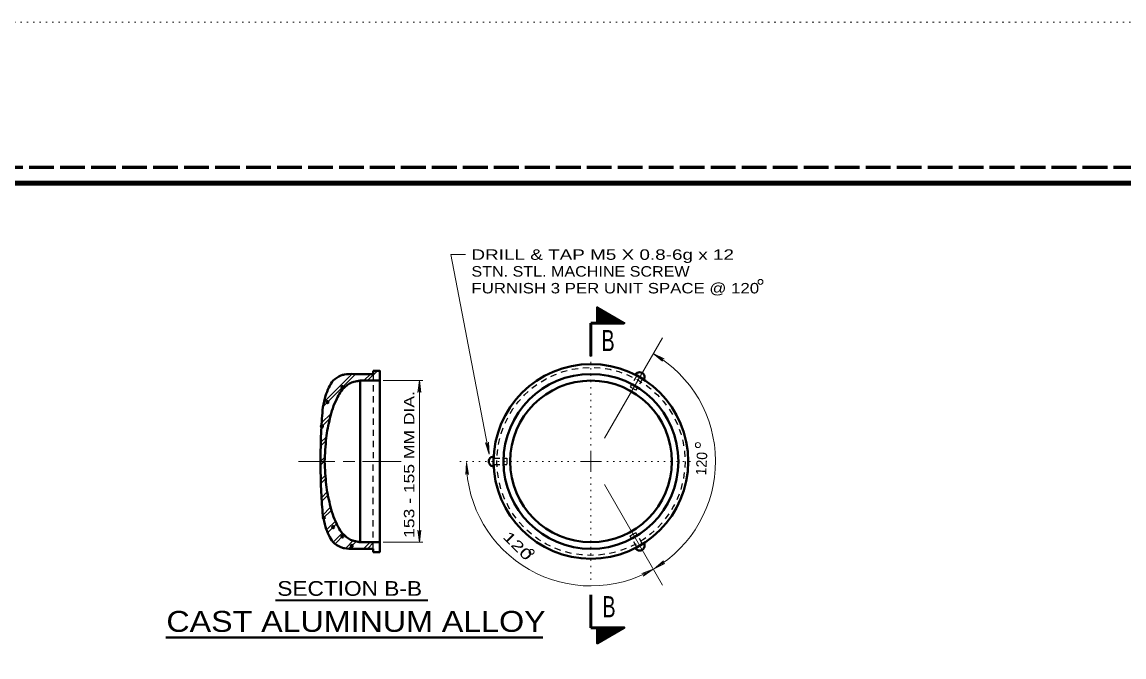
# Model space of a CAD drawing. Extents: x 312583 to 312854, y 144419 to 144597.
# Drawn here: x 312691.9 to 312772, y 144550.7 to 144596.8 of the extents above; entities that cross this region are included whole.
import ezdxf
from ezdxf.enums import TextEntityAlignment as Align

# ---------------------------------------------------------------- set-up
doc = ezdxf.new("R2010")
doc.units = 0
doc.header["$LTSCALE"] = 0.3
doc.header["$PDMODE"] = 32
doc.header["$PDSIZE"] = 0.15
for name, pattern in [('DOTTED', [1.5, 0.3, -1.2]), ('LONG_DASHED', [7.5, 6, -1.5]), ('SHORT_DASHED', [2.7, 1.5, -1.2])]:
    doc.linetypes.add(name, pattern=pattern)
for name, color, linetype, lineweight in [('1', 7, 'Continuous', 40), ('2', 7, 'Continuous', 13), ('62', 7, 'DOTTED', 13), ('63', 7, 'LONG_DASHED', 60)]:
    doc.layers.add(name, color=color, linetype=linetype, lineweight=lineweight)

msp = doc.modelspace()

# ---------------------------------------------------------------- linework, layer by layer
at = {"layer": '1', "lineweight": 13}
for p, q in [((312738.4358, 144573.8533), (312734.2191, 144566.5469)), ((312713.8488, 144568.9006), (312716.1564, 144571.2159)), ((312713.8871, 144569.2149), (312715.8498, 144571.1776)), ((312716.7621, 144570.7329), (312717.2451, 144571.2159)), ((312717.0304, 144570.7329), (312717.7511, 144571.4536)), ((312717.4368, 144571.4076), (312717.4828, 144571.4536)), ((312713.6724, 144567.3749), (312714.3011, 144568.0036)), ((312713.6801, 144567.6586), (312714.3701, 144568.3409)), ((312713.6341, 144565.9873), (312713.9791, 144566.3323)), ((312713.6418, 144566.2633), (312714.0251, 144566.6389)), ((312713.6034, 144564.8679), (312713.9178, 144565.1823)), ((312713.6111, 144564.5996), (312713.9024, 144564.8986)), ((312713.6264, 144563.5339), (312713.9638, 144563.8713)), ((312713.6341, 144563.2733), (312713.9868, 144563.6183)), ((312738.4358, 144555.8826), (312734.2191, 144563.1889)), ((312713.6571, 144562.2076), (312714.1248, 144562.6829)), ((312713.6724, 144561.9546), (312714.1631, 144562.4453)), ((312713.7798, 144560.9733), (312714.3164, 144561.5176)), ((312713.8028, 144560.7356), (312714.3854, 144561.3106)), ((312714.0941, 144559.9383), (312714.6921, 144560.5286)), ((312714.1861, 144559.7543), (312714.7688, 144560.3369)), ((312714.5388, 144559.0259), (312715.1981, 144559.6853)), ((312714.6614, 144558.8726), (312715.3361, 144559.5549)), ((312715.4358, 144558.5659), (312716.0031, 144559.1333)), ((312715.6964, 144558.5583), (312716.2178, 144559.0719)), ((312716.7544, 144558.5353), (312717.2221, 144558.9953)), ((312717.0228, 144558.5276), (312717.4904, 144558.9953)), ((312717.8584, 144558.2746), (312717.9121, 144558.3359))]:
    msp.add_line(p, q, dxfattribs=at)
at = {"layer": '1'}
for p, q in [((312717.4368, 144571.2159), (312715.9954, 144571.2159)), ((312717.4368, 144571.2159), (312717.4368, 144571.4536)), ((312736.4731, 144571.1699), (312737.0941, 144570.8096)), ((312716.4784, 144570.7406), (312716.4784, 144564.8679)), ((312717.9121, 144570.7406), (312717.9121, 144564.8679)), ((312716.4784, 144558.9953), (312716.4784, 144564.8679)), ((312717.9121, 144558.9953), (312717.9121, 144564.8679)), ((312726.1768, 144564.5076), (312726.1768, 144565.2206)), ((312717.4368, 144558.5199), (312715.9954, 144558.5199)), ((312717.4368, 144558.5199), (312717.4368, 144558.2746)), ((312737.0941, 144558.9263), (312736.4731, 144558.5659))]:
    msp.add_line(p, q, dxfattribs=at)
at = {"layer": '1', "linetype": 'SHORT_DASHED', "lineweight": 25}
for p, q in [((312717.4368, 144571.2159), (312717.4368, 144564.8679)), ((312736.5728, 144571.1086), (312736.0974, 144570.2806)), ((312736.9868, 144570.8709), (312736.5114, 144570.0429)), ((312736.5114, 144570.0429), (312736.0974, 144570.2806)), ((312717.4368, 144558.5199), (312717.4368, 144564.8679)), ((312726.1768, 144565.1056), (312727.1351, 144565.1056)), ((312727.1351, 144565.1056), (312727.1351, 144564.6303)), ((312726.1768, 144564.6303), (312727.1351, 144564.6303)), ((312736.0974, 144559.4553), (312736.5114, 144559.6929)), ((312736.5804, 144558.6273), (312736.0974, 144559.4553)), ((312736.9868, 144558.8649), (312736.5114, 144559.6929))]:
    msp.add_line(p, q, dxfattribs=at)
at = {"layer": '1', "lineweight": 158}
msp.add_lwpolyline([(312616.5, 144423.1446), (312616.5, 144585.0846), (312849, 144585.0846)], dxfattribs=at)
at = {"layer": '1'}
for points in [[(312716.4784, 144570.7406), (312717.9121, 144570.7406), (312717.9121, 144571.4536), (312717.4368, 144571.4536)], [(312716.4784, 144558.9953), (312717.9121, 144558.9953), (312717.9121, 144558.2746), (312717.4368, 144558.2746)]]:
    msp.add_lwpolyline(points, dxfattribs=at)
for radius in [7.0687, 6.3499, 5.8708]:
    msp.add_circle((312733.2474, 144564.866), radius, dxfattribs=at)
at = {"layer": '1', "linetype": 'SHORT_DASHED', "lineweight": 25}
msp.add_circle((312733.2474, 144564.866), 6.8291, dxfattribs=at)
at = {"layer": '1'}
for centre, start, end in [((312736.7823, 144570.9907), 329.52448, 150.47552), ((312726.1757, 144564.8651), 89.52448, 270.47552), ((312736.784, 144558.7423), 209.52448, 30.47552)]:
    msp.add_arc(centre, 0.3575, start, end, dxfattribs=at)
for points in [[(312713.6034, 144564.8679), (312713.6264, 144566.2249), (312713.7108, 144567.9806), (312713.7874, 144568.8009), (312713.9714, 144569.6289), (312714.2091, 144570.2269), (312714.5311, 144570.7329), (312715.0831, 144571.1009), (312715.3438, 144571.1776), (312715.9954, 144571.2159)], [(312716.4784, 144570.7406), (312716.2484, 144570.6946), (312716.0338, 144570.6486), (312715.7118, 144570.5183), (312715.4204, 144570.3113), (312715.0371, 144569.8743), (312714.7918, 144569.4143), (312714.4928, 144568.7166), (312714.2934, 144567.9883), (312714.1324, 144567.2829), (312714.0251, 144566.5623), (312713.9024, 144564.8526)], [(312713.6034, 144564.8679), (312713.6264, 144563.5109), (312713.7108, 144561.7553), (312713.7874, 144560.9349), (312713.9714, 144560.1069), (312714.2091, 144559.5013), (312714.5311, 144559.0029), (312715.0831, 144558.6349), (312715.3438, 144558.5583), (312715.9954, 144558.5199)], [(312716.4784, 144558.9953), (312716.2484, 144559.0413), (312716.0338, 144559.0873), (312715.7118, 144559.2176), (312715.4204, 144559.4246), (312715.0371, 144559.8539), (312714.7918, 144560.3139), (312714.4928, 144561.0116), (312714.2934, 144561.7476), (312714.1324, 144562.4529), (312714.0251, 144563.1736), (312713.9024, 144564.8526)]]:
    msp.add_spline(points, degree=3, dxfattribs=at)
for p in [(312715.1981, 144570.2576), (312714.1171, 144569.1766), (312713.7108, 144567.4133), (312713.8488, 144560.7739), (312714.5234, 144560.0916), (312715.1981, 144559.4169), (312715.8804, 144558.7346)]:
    msp.add_point(p, dxfattribs=at)
at = {"layer": '2'}
for p, q in [((312724.1451, 144579.8946), (312723.0794, 144579.8946)), ((312725.8624, 144565.3816), (312723.0794, 144579.8946)), ((312737.7688, 144572.7033), (312738.4434, 144572.1436)), ((312737.7688, 144572.7033), (312738.5584, 144572.3199)), ((312738.4434, 144572.1436), (312738.2671, 144572.3813)), ((312738.5584, 144572.3199), (312738.2671, 144572.3813)), ((312718.1574, 144570.7406), (312721.0324, 144570.7406)), ((312720.7871, 144570.7406), (312720.6798, 144569.8743)), ((312720.7871, 144558.9953), (312720.7871, 144570.7406)), ((312720.7871, 144570.7406), (312720.8944, 144569.8743)), ((312720.6798, 144569.8743), (312720.7871, 144570.1503)), ((312720.8944, 144569.8743), (312720.7871, 144570.1503)), ((312725.5941, 144566.2173), (312725.7474, 144565.9643)), ((312725.8624, 144565.3816), (312725.5941, 144566.2173)), ((312725.8011, 144566.2556), (312725.7474, 144565.9643)), ((312725.8624, 144565.3816), (312725.8011, 144566.2556)), ((312733.2454, 144564.8679), (312733.2454, 144565.6346)), ((312712.0011, 144564.8679), (312714.6538, 144564.8679)), ((312715.2441, 144564.8679), (312716.0951, 144564.8679)), ((312716.6548, 144564.8679), (312719.4608, 144564.8679)), ((312724.2064, 144564.7836), (312724.1528, 144563.9173)), ((312724.2064, 144564.7836), (312724.3598, 144563.9249)), ((312733.2454, 144564.8679), (312732.4788, 144564.8679)), ((312733.2454, 144564.8679), (312732.4788, 144564.8679)), ((312733.2454, 144564.8679), (312733.2454, 144564.1013)), ((312733.2454, 144564.8679), (312734.0121, 144564.8679)), ((312724.1528, 144563.9173), (312724.2371, 144564.2009)), ((312724.3598, 144563.9249), (312724.2371, 144564.2009)), ((312720.6798, 144559.8616), (312720.7871, 144559.5856)), ((312720.7871, 144558.9953), (312720.6798, 144559.8616)), ((312720.8944, 144559.8616), (312720.7871, 144559.5856)), ((312720.7871, 144558.9953), (312720.8944, 144559.8616)), ((312718.1574, 144558.9953), (312721.0324, 144558.9953)), ((312737.8378, 144557.0709), (312738.5048, 144557.6459)), ((312738.5048, 144557.6459), (312738.3361, 144557.4006)), ((312737.7688, 144557.0326), (312736.9484, 144556.7336)), ((312736.9484, 144556.7336), (312737.2474, 144556.7643)), ((312737.7688, 144557.0326), (312737.0481, 144556.5419)), ((312737.0481, 144556.5419), (312737.2474, 144556.7643)), ((312737.8378, 144557.0709), (312738.6198, 144557.4619)), ((312738.6198, 144557.4619), (312738.3361, 144557.4006))]:
    msp.add_line(p, q, dxfattribs=at)
at = {"layer": '2', "lineweight": 35}
for p, q in [((312733.7208, 144575.9923), (312733.7361, 144576.0076)), ((312733.7208, 144575.9463), (312733.7591, 144575.9999)), ((312733.7208, 144575.8926), (312733.7744, 144575.9846)), ((312733.7208, 144575.8466), (312733.7974, 144575.9693)), ((312733.7208, 144575.7929), (312733.8204, 144575.9616)), ((312733.7208, 144575.7546), (312733.8358, 144575.9463)), ((312733.7208, 144575.7009), (312733.8588, 144575.9386)), ((312733.7208, 144575.6549), (312733.8818, 144575.9233)), ((312733.7208, 144575.6089), (312733.8971, 144575.9156)), ((312733.7208, 144575.5629), (312733.9278, 144575.9003)), ((312733.7208, 144575.5093), (312733.9431, 144575.8926)), ((312733.7208, 144575.4633), (312733.9661, 144575.8773)), ((312733.7208, 144575.4173), (312733.9891, 144575.8696)), ((312733.7208, 144575.3636), (312734.0044, 144575.8543)), ((312733.7208, 144575.3176), (312734.0274, 144575.8466)), ((312733.7208, 144575.2716), (312734.0428, 144575.8313)), ((312733.7208, 144575.2179), (312734.0658, 144575.8159)), ((312733.7208, 144575.1719), (312734.0888, 144575.8083)), ((312733.7208, 144575.1259), (312734.1041, 144575.7929)), ((312733.7208, 144575.0799), (312734.1271, 144575.7776)), ((312733.7208, 144575.0263), (312734.1501, 144575.7699)), ((312733.7208, 144574.9879), (312734.1654, 144575.7546)), ((312733.7208, 144574.9343), (312734.1961, 144575.7469)), ((312733.7361, 144574.9113), (312734.2114, 144575.7316)), ((312733.7668, 144574.9113), (312734.2344, 144575.7239)), ((312733.7974, 144574.9113), (312734.2574, 144575.7086)), ((312733.8204, 144574.9113), (312734.2728, 144575.7009)), ((312733.8511, 144574.9113), (312734.2958, 144575.6856)), ((312733.8741, 144574.9189), (312734.3188, 144575.6779)), ((312733.9048, 144574.9189), (312734.3341, 144575.6626)), ((312733.9278, 144574.9113), (312734.3571, 144575.6549)), ((312733.9584, 144574.9113), (312734.3801, 144575.6396)), ((312733.9891, 144574.9113), (312734.3954, 144575.6243)), ((312734.0121, 144574.9113), (312734.4184, 144575.6166)), ((312734.0428, 144574.9113), (312734.4414, 144575.6013)), ((312734.0734, 144574.9113), (312734.4644, 144575.5859)), ((312734.0964, 144574.9113), (312734.4798, 144575.5783)), ((312734.1271, 144574.9189), (312734.5028, 144575.5629)), ((312734.1578, 144574.9113), (312734.5258, 144575.5553)), ((312734.1808, 144574.9113), (312734.5411, 144575.5399)), ((312734.2038, 144574.9113), (312734.5641, 144575.5323)), ((312734.2344, 144574.9113), (312734.5871, 144575.5169)), ((312734.2651, 144574.9113), (312734.6024, 144575.5093)), ((312734.2958, 144574.9113), (312734.6254, 144575.4939)), ((312734.3188, 144574.9113), (312734.6484, 144575.4863)), ((312734.3494, 144574.9113), (312734.6638, 144575.4709)), ((312734.3724, 144574.9189), (312734.6944, 144575.4633)), ((312734.4031, 144574.9113), (312734.7098, 144575.4479)), ((312734.4261, 144574.9113), (312734.7328, 144575.4326)), ((312734.4568, 144574.9113), (312734.7558, 144575.4249)), ((312734.4874, 144574.9113), (312734.7711, 144575.4096)), ((312734.5104, 144574.9113), (312734.7941, 144575.4019)), ((312734.5411, 144574.9113), (312734.8171, 144575.3866)), ((312734.5718, 144574.9113), (312734.8324, 144575.3789)), ((312734.5948, 144574.9113), (312734.8554, 144575.3636)), ((312734.6254, 144574.9113), (312734.8784, 144575.3559)), ((312734.6561, 144574.9113), (312734.8938, 144575.3406)), ((312734.6791, 144574.9113), (312734.9168, 144575.3329)), ((312734.7021, 144574.9113), (312734.9398, 144575.3176)), ((312734.7328, 144574.9113), (312734.9628, 144575.3099)), ((312734.7634, 144574.9113), (312734.9781, 144575.2946)), ((312734.7941, 144574.9113), (312735.0011, 144575.2793)), ((312734.8171, 144574.9113), (312735.0241, 144575.2716)), ((312734.8478, 144574.9113), (312735.0394, 144575.2563)), ((312734.8708, 144574.9113), (312735.0624, 144575.2409)), ((312734.9014, 144574.9113), (312735.0854, 144575.2333)), ((312734.9244, 144574.9113), (312735.1008, 144575.2179)), ((312734.9551, 144574.9113), (312735.1238, 144575.2103)), ((312734.9858, 144574.9113), (312735.1468, 144575.1949)), ((312735.0088, 144574.9113), (312735.1621, 144575.1873)), ((312735.0394, 144574.9113), (312735.1928, 144575.1719)), ((312735.0624, 144574.9113), (312735.2081, 144575.1643)), ((312735.0931, 144574.9113), (312735.2311, 144575.1489)), ((312735.1238, 144574.9113), (312735.2541, 144575.1413)), ((312735.1468, 144574.9113), (312735.2694, 144575.1259)), ((312735.1774, 144574.9113), (312735.2924, 144575.1183)), ((312735.2004, 144574.9113), (312735.3154, 144575.1029)), ((312735.2311, 144574.9113), (312735.3308, 144575.0876)), ((312735.2618, 144574.9113), (312735.3538, 144575.0799)), ((312735.2924, 144574.9113), (312735.3768, 144575.0646)), ((312735.3154, 144574.9113), (312735.3921, 144575.0493)), ((312735.3461, 144574.9113), (312735.4151, 144575.0416)), ((312735.3691, 144574.9113), (312735.4381, 144575.0263)), ((312735.3921, 144574.9113), (312735.4611, 144575.0186)), ((312735.4228, 144574.9113), (312735.4764, 144575.0033)), ((312735.4534, 144574.9113), (312735.4994, 144574.9956)), ((312735.4841, 144574.9113), (312735.5224, 144574.9803)), ((312735.5071, 144574.9113), (312735.5378, 144574.9726)), ((312735.5378, 144574.9113), (312735.5608, 144574.9573)), ((312735.5608, 144574.9113), (312735.5838, 144574.9496)), ((312735.5914, 144574.9113), (312735.5991, 144574.9343)), ((312735.6221, 144574.9113), (312735.6221, 144574.9266)), ((312710.3272, 144554.7939), (312721.3972, 144554.7939)), ((312733.7208, 144552.7623), (312734.1961, 144551.9496)), ((312733.7361, 144552.7853), (312734.2114, 144551.9649)), ((312733.7668, 144552.7853), (312734.2344, 144551.9726)), ((312733.7974, 144552.7853), (312734.2574, 144551.9879)), ((312733.8204, 144552.7853), (312734.2728, 144551.9956)), ((312733.8511, 144552.7853), (312734.2958, 144552.0109)), ((312733.8741, 144552.7776), (312734.3188, 144552.0186)), ((312733.9048, 144552.7776), (312734.3341, 144552.0339)), ((312733.9278, 144552.7853), (312734.3571, 144552.0416)), ((312733.9584, 144552.7853), (312734.3801, 144552.0569)), ((312733.9891, 144552.7853), (312734.3954, 144552.0723)), ((312734.0121, 144552.7853), (312734.4184, 144552.0799)), ((312734.0428, 144552.7853), (312734.4414, 144552.0953)), ((312734.0734, 144552.7853), (312734.4644, 144552.1106)), ((312734.0964, 144552.7853), (312734.4798, 144552.1183)), ((312734.1271, 144552.7776), (312734.5028, 144552.1336)), ((312734.1578, 144552.7853), (312734.5258, 144552.1413)), ((312734.1808, 144552.7853), (312734.5411, 144552.1566)), ((312734.2038, 144552.7853), (312734.5641, 144552.1643)), ((312734.2344, 144552.7853), (312734.5871, 144552.1796)), ((312734.2651, 144552.7853), (312734.6024, 144552.1873)), ((312734.2958, 144552.7853), (312734.6254, 144552.2026)), ((312734.3188, 144552.7853), (312734.6484, 144552.2103)), ((312734.3494, 144552.7853), (312734.6638, 144552.2256)), ((312734.3724, 144552.7776), (312734.6944, 144552.2333)), ((312734.4031, 144552.7853), (312734.7098, 144552.2486)), ((312734.4261, 144552.7853), (312734.7328, 144552.2639)), ((312734.4568, 144552.7853), (312734.7558, 144552.2716)), ((312734.4874, 144552.7853), (312734.7711, 144552.2869)), ((312734.5104, 144552.7853), (312734.7941, 144552.2946)), ((312734.5411, 144552.7853), (312734.8171, 144552.3099)), ((312734.5718, 144552.7853), (312734.8324, 144552.3176)), ((312734.5948, 144552.7853), (312734.8554, 144552.3329)), ((312734.6254, 144552.7853), (312734.8784, 144552.3406)), ((312734.6561, 144552.7853), (312734.8938, 144552.3559)), ((312734.6791, 144552.7853), (312734.9168, 144552.3636)), ((312734.7021, 144552.7853), (312734.9398, 144552.3789)), ((312734.7328, 144552.7853), (312734.9628, 144552.3866)), ((312734.7634, 144552.7853), (312734.9781, 144552.4019)), ((312734.7941, 144552.7853), (312735.0011, 144552.4173)), ((312734.8171, 144552.7853), (312735.0241, 144552.4249)), ((312734.8478, 144552.7853), (312735.0394, 144552.4403)), ((312734.8708, 144552.7853), (312735.0624, 144552.4556)), ((312734.9014, 144552.7853), (312735.0854, 144552.4633)), ((312734.9244, 144552.7853), (312735.1008, 144552.4786)), ((312734.9551, 144552.7853), (312735.1238, 144552.4863)), ((312734.9858, 144552.7853), (312735.1468, 144552.5016)), ((312735.0088, 144552.7853), (312735.1621, 144552.5093)), ((312735.0394, 144552.7853), (312735.1928, 144552.5246)), ((312735.0624, 144552.7853), (312735.2081, 144552.5323)), ((312735.0931, 144552.7853), (312735.2311, 144552.5476)), ((312735.1238, 144552.7853), (312735.2541, 144552.5553)), ((312735.1468, 144552.7853), (312735.2694, 144552.5706)), ((312735.1774, 144552.7853), (312735.2924, 144552.5783)), ((312735.2004, 144552.7853), (312735.3154, 144552.5936)), ((312735.2311, 144552.7853), (312735.3308, 144552.6089)), ((312735.2618, 144552.7853), (312735.3538, 144552.6166)), ((312735.2924, 144552.7853), (312735.3768, 144552.6319)), ((312735.3154, 144552.7853), (312735.3921, 144552.6473)), ((312735.3461, 144552.7853), (312735.4151, 144552.6549)), ((312735.3691, 144552.7853), (312735.4381, 144552.6703)), ((312735.3921, 144552.7853), (312735.4611, 144552.6779)), ((312735.4228, 144552.7853), (312735.4764, 144552.6933)), ((312735.4534, 144552.7853), (312735.4994, 144552.7009)), ((312735.4841, 144552.7853), (312735.5224, 144552.7163)), ((312735.5071, 144552.7853), (312735.5378, 144552.7239)), ((312735.5378, 144552.7853), (312735.5608, 144552.7393)), ((312735.5608, 144552.7853), (312735.5838, 144552.7469)), ((312735.5914, 144552.7853), (312735.5991, 144552.7623)), ((312735.6221, 144552.7853), (312735.6221, 144552.7699)), ((312733.7208, 144552.7086), (312734.1654, 144551.9419)), ((312733.7208, 144552.6703), (312734.1501, 144551.9266)), ((312733.7208, 144552.6166), (312734.1271, 144551.9189)), ((312733.7208, 144552.5706), (312734.1041, 144551.9036)), ((312733.7208, 144552.5246), (312734.0888, 144551.8883)), ((312733.7208, 144552.4786), (312734.0658, 144551.8806)), ((312733.7208, 144552.4249), (312734.0428, 144551.8653)), ((312733.7208, 144552.3789), (312734.0274, 144551.8499)), ((312733.7208, 144552.3329), (312734.0044, 144551.8423)), ((312733.7208, 144552.2793), (312733.9891, 144551.8269)), ((312733.7208, 144552.2333), (312733.9661, 144551.8193)), ((312733.7208, 144552.1873), (312733.9431, 144551.8039)), ((312733.7208, 144552.1336), (312733.9278, 144551.7963)), ((312733.7208, 144552.0876), (312733.8971, 144551.7809)), ((312733.7208, 144552.0416), (312733.8818, 144551.7733)), ((312733.7208, 144551.9956), (312733.8588, 144551.7579)), ((312733.7208, 144551.9419), (312733.8358, 144551.7503)), ((312733.7208, 144551.9036), (312733.8204, 144551.7349)), ((312733.7208, 144551.8499), (312733.7974, 144551.7273)), ((312733.7208, 144551.8039), (312733.7744, 144551.7119)), ((312733.7208, 144551.7503), (312733.7591, 144551.6966)), ((312733.7208, 144551.7043), (312733.7361, 144551.6889))]:
    msp.add_line(p, q, dxfattribs=at)
at = {"layer": '2', "lineweight": 53}
for p, q in [((312733.2454, 144572.5193), (312733.2454, 144574.9113)), ((312733.7208, 144574.9113), (312733.2454, 144574.9113)), ((312733.2454, 144555.1773), (312733.2454, 144552.7853)), ((312733.7208, 144552.7853), (312733.2454, 144552.7853))]:
    msp.add_line(p, q, dxfattribs=at)
at = {"layer": '2', "linetype": 'DOTTED'}
for p, q in [((312733.2454, 144566.0179), (312733.2454, 144573.6846)), ((312732.0954, 144564.8679), (312723.3861, 144564.8679)), ((312734.3954, 144564.8679), (312740.6284, 144564.8679)), ((312733.2454, 144563.7179), (312733.2454, 144556.1663))]:
    msp.add_line(p, q, dxfattribs=at)
at = {"layer": '2', "lineweight": 40}
msp.add_line((312702.3688, 144552.0646), (312729.7533, 144552.0646), dxfattribs=at)
at = {"layer": '2', "lineweight": 53}
for points in [[(312733.7208, 144574.9113), (312733.7208, 144576.0229), (312735.6374, 144574.9113)], [(312733.7208, 144552.7853), (312733.7208, 144551.6736), (312735.6374, 144552.7853)]]:
    msp.add_lwpolyline(points, close=True, dxfattribs=at)
at = {"layer": '2'}
for centre in [(312745.5571, 144577.9083), (312741.0141, 144566.0536), (312728.9329, 144558.2995)]:
    msp.add_circle(centre, 0.1797, dxfattribs=at)
for start, end in [(300.50993, 59.99393), (180.50993, 299.99393)]:
    msp.add_arc((312733.2474, 144564.866), 9.0451, start, end, dxfattribs=at)
at = {"layer": '62'}
msp.add_line((312601.2, 144596.7846), (312853.5, 144596.7846), dxfattribs=at)
at = {"layer": '63'}
msp.add_line((312851.75, 144586.2246), (312583.526, 144586.2246), dxfattribs=at)

# ---------------------------------------------------------------- texts
at = {"layer": '2'}
for s, width, p in [('DRILL & TAP M5 X 0.8-6g x 12', 1.35, (312724.5668, 144579.5103)), ('STN. STL. MACHINE SCREW', 1.15, (312724.5668, 144578.2903)), ('FURNISH 3 PER UNIT SPACE @ 120', 1.2, (312724.5668, 144577.0703))]:
    msp.add_text(s, height=0.76, dxfattribs=dict(at, width=width)).set_placement(p)
for s, height, width, p in [('B', 1.533, 0.7, (312734.4874, 144572.8796)), ('SECTION B-B', 1.07, 1.15, (312715.7244, 144555.1027)), ('B', 1.533, 0.7, (312734.5564, 144553.5443)), ('CAST ALUMINUM ALLOY', 1.52, 1.15, (312716.1838, 144552.4846))]:
    msp.add_text(s, height=height, dxfattribs=dict(at, width=width)).set_placement(p, align=Align.CENTER)
for s, rotation, width, p in [('153 - 155 MM DIA.', 90, 1.25, (312720.4203, 144559.3119)), ('120', 315, 1.45, (312726.7985, 144559.3341))]:
    msp.add_text(s, height=0.76, rotation=rotation, dxfattribs=dict(at, width=width)).set_placement(p)
msp.add_text('120', height=0.76, rotation=87, dxfattribs=at).set_placement((312741.6093, 144563.8389))

doc.saveas('drawing.dxf')
